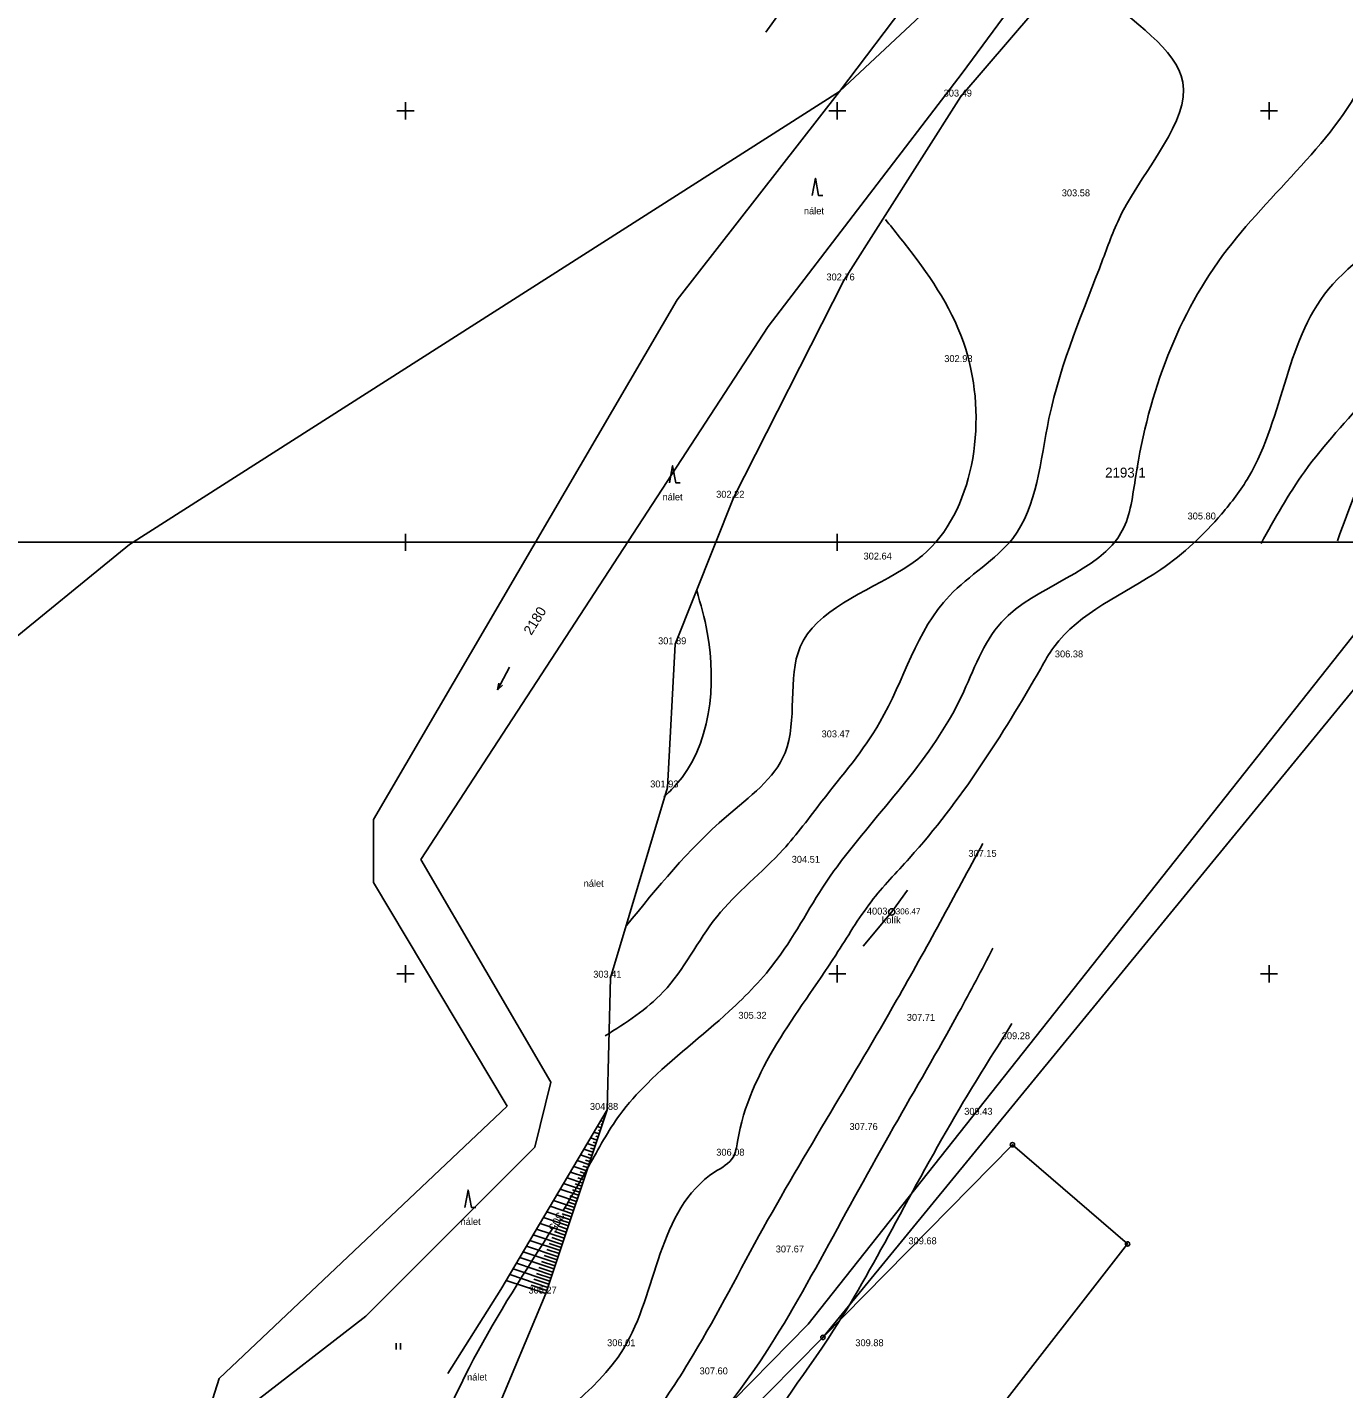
# Model space of a CAD drawing. Extents: x -504375 to -503125, y -1118000 to -1116474.
# Drawn here: x -503693.8 to -503541.3, y -1117098.1 to -1116940.3 of the extents above; entities that cross this region are included whole.
import ezdxf

# ---------------------------------------------------------------- set-up
doc = ezdxf.new("R2010")
doc.units = 0
for name, color, linetype in [('Druhy povrchů', 7, 'Continuous'), ('Podkladové mapy', 7, 'Continuous'), ('Síť dekadická', 7, 'Continuous'), ('Vrstva 34', 7, 'Continuous'), ('Vrstva 48', 7, 'Continuous'), ('Výškopis', 7, 'Continuous'), ('Výšky bod_ pole', 7, 'Continuous'), ('Výšky bodů plotr', 7, 'Continuous'), ('Čísla bod_ pole', 7, 'Continuous')]:
    doc.layers.add(name, color=color, linetype=linetype)

msp = doc.modelspace()

# ---------------------------------------------------------------- linework, layer by layer
at = {"layer": 'Druhy povrchů'}
for p, q in [((-503651.096, -1117093.521), (-503651.096, -1117092.771)), ((-503650.596, -1117093.521), (-503650.596, -1117092.771))]:
    msp.add_line(p, q, dxfattribs=at)
for points in [[(-503608.29, -1116940.921), (-503586.95, -1116911.2)], [(-503626.65, -1117065.74), (-503626.27, -1117050.43), (-503619.67, -1117028.39), (-503618.76, -1117011.81), (-503612.03, -1116994.83), (-503599.26, -1116969.66), (-503585.68, -1116948.36), (-503569.03, -1116928.88)], [(-503602.917, -1116959.834), (-503602.542, -1116957.834), (-503602.167, -1116959.834), (-503601.667, -1116959.834)], [(-503619.45, -1116993.122), (-503619.075, -1116991.122), (-503618.7, -1116993.122), (-503618.2, -1116993.122)], [(-503643.134, -1117077.037), (-503642.759, -1117075.037), (-503642.384, -1117077.037), (-503641.884, -1117077.037)]]:
    msp.add_lwpolyline(points, dxfattribs=at)
at = {"layer": 'Podkladové mapy'}
for p, q in [((-503599.74, -1116947.77), (-503559.03, -1116909.64)), ((-503559.03, -1116909.64), (-503585.52, -1116945.65)), ((-503582.63, -1116925.15), (-503599.74, -1116947.77)), ((-503585.52, -1116945.65), (-503608.01, -1116975)), ((-503599.74, -1116947.77), (-503681.99, -1117000.24)), ((-503599.74, -1116947.77), (-503618.54, -1116971.91)), ((-503618.54, -1116971.91), (-503653.73, -1117032.11)), ((-503608.01, -1116975), (-503648.24, -1117036.74)), ((-503681.99, -1117000.24), (-503736.12, -1117044.39)), ((-503603.38, -1117090.56), (-503539.71, -1117010.12)), ((-503637.952, -1117014.442), (-503639.348, -1117017.098)), ((-503639.348, -1117017.098), (-503639.22, -1117016.318)), ((-503639.348, -1117017.098), (-503638.778, -1117016.55)), ((-503539.88, -1117016.68), (-503601.67, -1117092.1)), ((-503653.73, -1117032.11), (-503653.73, -1117039.4)), ((-503648.24, -1117036.74), (-503633.18, -1117062.52)), ((-503653.73, -1117039.4), (-503638.23, -1117065.31)), ((-503633.18, -1117062.52), (-503635.02, -1117070.06)), ((-503638.23, -1117065.31), (-503671.6, -1117096.86)), ((-503635.02, -1117070.06), (-503654.6, -1117089.64)), ((-503601.67, -1117092.1), (-503579.71, -1117069.78)), ((-503579.71, -1117069.78), (-503566.38, -1117081.28)), ((-503566.38, -1117081.28), (-503584.24, -1117104.21)), ((-503654.6, -1117089.64), (-503668.48, -1117100.36)), ((-503629.16, -1117116.82), (-503603.38, -1117090.56)), ((-503601.67, -1117092.1), (-503628.2, -1117118.94)), ((-503671.6, -1117096.86), (-503676.34, -1117111.82))]:
    msp.add_line(p, q, dxfattribs=at)
for centre, radius in [((-503579.71, -1117069.78), 0.25), ((-503579.71, -1117069.78), 0.005), ((-503566.38, -1117081.28), 0.25), ((-503566.38, -1117081.28), 0.005), ((-503601.67, -1117092.1), 0.25), ((-503601.67, -1117092.1), 0.005)]:
    msp.add_circle(centre, radius, dxfattribs=at)
at = {"layer": 'Síť dekadická'}
for points in [[(-503125, -1116500), (-503125, -1117000), (-503750, -1117000), (-503750, -1116500)], [(-503125, -1117000), (-503125, -1117500), (-503750, -1117500), (-503750, -1117000)]]:
    msp.add_lwpolyline(points, close=True, dxfattribs=at)
at = {"layer": 'Vrstva 34'}
for p, q in [((-503649, -1116950), (-503651, -1116950)), ((-503650, -1116949), (-503650, -1116951)), ((-503599, -1116950), (-503601, -1116950)), ((-503600, -1116949), (-503600, -1116951)), ((-503549, -1116950), (-503551, -1116950)), ((-503550, -1116949), (-503550, -1116951)), ((-503650, -1116999), (-503650, -1117001)), ((-503600, -1116999), (-503600, -1117001)), ((-503649, -1117000), (-503651, -1117000)), ((-503599, -1117000), (-503601, -1117000)), ((-503650, -1117049), (-503650, -1117051)), ((-503600, -1117049), (-503600, -1117051)), ((-503550, -1117049), (-503550, -1117051)), ((-503649, -1117050), (-503651, -1117050)), ((-503599, -1117050), (-503601, -1117050)), ((-503549, -1117050), (-503551, -1117050))]:
    msp.add_line(p, q, dxfattribs=at)
msp.add_lwpolyline([(-503819.807, -1117000), (-503275.634, -1117000)], dxfattribs=at)
at = {"layer": 'Vrstva 48'}
for points in [[(-503604.648, -1116893.017), (-503585.281, -1116877.629), (-503564.204, -1116856.163), (-503559.141, -1116846.411), (-503555.47, -1116841.092), (-503545.09, -1116825.515), (-503541.545, -1116820.955), (-503537.748, -1116809.05), (-503527.661, -1116795.622), (-503512.228, -1116780.775), (-503494.197, -1116771.273), (-503473.272, -1116763.329), (-503471.937, -1116764.072), (-503472.777, -1116780.406), (-503472.777, -1116784.258), (-503469.477, -1116780.647), (-503453.941, -1116763.075), (-503453.185, -1116762.352), (-503453.185, -1116762.868), (-503453.975, -1116764.072), (-503471.299, -1116785.427), (-503472.33, -1116786.837), (-503470.852, -1116786.39), (-503455.075, -1116781.507), (-503451.26, -1116777.243), (-503444.179, -1116769.093), (-503443.526, -1116769.574), (-503443.526, -1116770.571), (-503444.695, -1116772.291), (-503475.689, -1116813.651), (-503482.752, -1116823.597), (-503483.629, -1116833.318), (-503494.224, -1116852.196), (-503500.83, -1116876.786), (-503505.671, -1116884.199), (-503502.737, -1116897.996), (-503507.864, -1116915.207), (-503507.864, -1116918.075), (-503510.659, -1116921.875), (-503514.672, -1116929.547), (-503521.782, -1116946.335), (-503523.508, -1116955.336), (-503526.664, -1116975.16), (-503536.264, -1116987.26), (-503542.078, -1116999.845)], [(-503595.76, -1116904.33), (-503567.553, -1116880.477), (-503564.659, -1116878.465), (-503551.807, -1116863.496), (-503544.154, -1116853.288), (-503519.921, -1116831.988), (-503513.226, -1116822.631), (-503501.21, -1116822.631), (-503499.538, -1116822.631), (-503498.221, -1116820.86), (-503490.256, -1116808.462), (-503490.097, -1116808.462), (-503490.242, -1116808.76), (-503498.304, -1116822.118), (-503497.349, -1116823.505), (-503494.998, -1116824.802), (-503494.566, -1116824.802), (-503486.255, -1116822.916), (-503485.421, -1116822.675), (-503484.37, -1116821.039), (-503476.855, -1116810.755), (-503475.486, -1116809.268), (-503476.662, -1116811.094), (-503489.122, -1116830.174), (-503489.781, -1116831.15), (-503492.54, -1116830.63), (-503502.814, -1116846.355), (-503503.817, -1116849.106), (-503512.403, -1116878.631), (-503514.977, -1116882.212), (-503509.347, -1116898.468), (-503509.347, -1116900.238), (-503513.047, -1116914.643), (-503520.593, -1116930.622), (-503522.926, -1116936.361), (-503526.804, -1116946.842), (-503527.79, -1116953.008), (-503531.841, -1116973.659), (-503545.886, -1116991.815), (-503550.918, -1117000.124)], [(-503583.436, -1116916.735), (-503565.222, -1116898.002), (-503545.734, -1116881.633), (-503534.572, -1116870.778), (-503513.205, -1116846.809), (-503510.867, -1116843.732), (-503510.418, -1116843.732), (-503511.603, -1116846.232), (-503518.586, -1116862.77), (-503523.84, -1116880.397), (-503523.84, -1116881.294), (-503515.357, -1116898.665), (-503516.275, -1116901.249), (-503527.394, -1116929.845), (-503527.394, -1116936.169), (-503527.485, -1116936.022), (-503531.377, -1116947.63), (-503532.293, -1116950.302), (-503533.896, -1116960.764), (-503542.598, -1116970.081), (-503552.37, -1116992.445), (-503555.496, -1116996.72), (-503562.532, -1117003.134), (-503574.935, -1117012.154), (-503576.446, -1117014.604), (-503591.634, -1117036.568), (-503596.086, -1117041.635), (-503600.171, -1117047.806), (-503611.566, -1117069.423), (-503612.057, -1117071.221), (-503614.181, -1117072.938), (-503624.76, -1117093.42), (-503637.766, -1117106.652), (-503639.522, -1117109.013), (-503645.943, -1117120.982), (-503647.205, -1117123.178), (-503648.851, -1117124.99), (-503653.281, -1117132.788), (-503655.18, -1117135.25), (-503664.808, -1117144.375), (-503670.8, -1117145.499), (-503672.957, -1117151.15), (-503675.518, -1117162.241), (-503680.888, -1117175.407), (-503686.593, -1117176.265), (-503690.913, -1117183.112)], [(-503575.161, -1116925.677), (-503571.61, -1116920.286), (-503561.49, -1116904.84), (-503546.317, -1116891.936), (-503543.581, -1116890.008), (-503545.449, -1116892.274), (-503560.054, -1116907.893), (-503567.245, -1116921.98), (-503572.354, -1116932.827), (-503569.7, -1116936.145), (-503559.991, -1116946.69), (-503567.028, -1116961.847), (-503569.227, -1116967.176), (-503575.482, -1116985.657), (-503579.685, -1116999.542), (-503587.015, -1117006.191), (-503595.059, -1117020.842), (-503601.786, -1117029.99), (-503606.272, -1117035.599), (-503613.948, -1117043.366), (-503620.158, -1117052.082), (-503626.886, -1117057.173)], [(-503536.643, -1116939.897), (-503538.176, -1116944.585), (-503554.835, -1116966.082), (-503565.428, -1116992.282), (-503566.988, -1116998.644), (-503580.982, -1117009.239), (-503585.615, -1117017.847), (-503599.496, -1117036.863), (-503600.903, -1117038.792), (-503606.947, -1117048.279), (-503612.516, -1117054.325), (-503622.032, -1117062.711), (-503625.19, -1117066.316), (-503628.794, -1117072.271), (-503631.697, -1117077.316)], [(-503624.405, -1117044.39), (-503612.833, -1117031.761), (-503606.053, -1117024.393), (-503604.3, -1117012.114), (-503592.377, -1117003.109), (-503590.138, -1117001.513), (-503584.884, -1116978.453), (-503591.259, -1116966.607), (-503594.412, -1116962.612)], [(-503620.074, -1117029.483), (-503618.701, -1117028.109), (-503615.064, -1117010.433), (-503616.288, -1117005.569)], [(-503681.581, -1117189.358), (-503677.862, -1117181.382), (-503666.722, -1117185.997), (-503660.312, -1117176.769), (-503662.273, -1117171.205), (-503665.544, -1117166.288), (-503664.496, -1117159.63), (-503663.424, -1117157.82), (-503656.724, -1117146.894), (-503651.699, -1117143.274), (-503642.136, -1117131.351), (-503640.456, -1117128.532), (-503633.339, -1117117.852), (-503629.848, -1117112.023), (-503622.694, -1117102.978), (-503617.219, -1117095.012), (-503609.076, -1117080.347), (-503600.768, -1117066.026), (-503593.131, -1117053.049), (-503583.142, -1117034.879)], [(-503670.377, -1117191.619), (-503669.68, -1117189.038), (-503667.476, -1117187.838), (-503659.224, -1117178.665), (-503659.729, -1117171.664), (-503658.467, -1117166.241), (-503646.499, -1117149.509), (-503636.524, -1117137.367), (-503628.369, -1117122.514), (-503620.153, -1117109.423), (-503610.19, -1117096.668), (-503601.485, -1117082.212), (-503593.478, -1117067.759), (-503585.924, -1117054.445), (-503581.971, -1117047.028)], [(-503663.774, -1117189.171), (-503657.669, -1117182.299), (-503653.803, -1117173.825), (-503650.734, -1117168.851), (-503649.206, -1117166.706), (-503639.945, -1117154.236), (-503631.523, -1117142.215), (-503623.535, -1117130.705), (-503616.437, -1117119.955), (-503611.15, -1117107.935), (-503600.425, -1117091.261), (-503593.212, -1117078.753), (-503585.366, -1117064.793), (-503579.769, -1117055.757)], [(-503632.866, -1117079.324), (-503648.483, -1117110.842), (-503649.96, -1117118.382), (-503650.49, -1117120.413), (-503659.36, -1117127.451), (-503663.602, -1117129.909)]]:
    msp.add_spline(points, degree=3, dxfattribs=at)
at = {"layer": 'Výškopis'}
for p, q in [((-503627.107, -1117067.105), (-503627.4, -1117067.007)), ((-503626.988, -1117066.75), (-503627.074, -1117066.721)), ((-503626.869, -1117066.394), (-503627.009, -1117066.347)), ((-503626.75, -1117066.038), (-503626.775, -1117066.03)), ((-503627.583, -1117068.528), (-503628.181, -1117068.328)), ((-503627.345, -1117067.816), (-503627.79, -1117067.667)), ((-503627.464, -1117068.172), (-503627.673, -1117068.102)), ((-503627.226, -1117067.461), (-503627.374, -1117067.411)), ((-503628.059, -1117069.95), (-503628.962, -1117069.648)), ((-503627.821, -1117069.239), (-503628.572, -1117068.988)), ((-503628.178, -1117070.306), (-503628.57, -1117070.175)), ((-503627.94, -1117069.595), (-503628.271, -1117069.484)), ((-503627.702, -1117068.883), (-503627.972, -1117068.793)), ((-503628.773, -1117072.084), (-503630.134, -1117071.628)), ((-503628.535, -1117071.373), (-503629.744, -1117070.968)), ((-503628.297, -1117070.661), (-503629.353, -1117070.308)), ((-503628.654, -1117071.728), (-503629.168, -1117071.556)), ((-503628.416, -1117071.017), (-503628.869, -1117070.865)), ((-503629.249, -1117073.506), (-503630.915, -1117072.948)), ((-503629.011, -1117072.795), (-503630.525, -1117072.288)), ((-503629.13, -1117073.151), (-503629.766, -1117072.938)), ((-503628.892, -1117072.439), (-503629.467, -1117072.247)), ((-503629.962, -1117075.64), (-503632.087, -1117074.929)), ((-503629.724, -1117074.929), (-503631.697, -1117074.269)), ((-503629.486, -1117074.218), (-503631.306, -1117073.609)), ((-503629.605, -1117074.573), (-503630.364, -1117074.319)), ((-503629.368, -1117073.862), (-503630.065, -1117073.629)), ((-503630.438, -1117077.063), (-503632.868, -1117076.249)), ((-503630.2, -1117076.351), (-503632.478, -1117075.589)), ((-503630.319, -1117076.707), (-503631.261, -1117076.392)), ((-503630.081, -1117075.996), (-503630.962, -1117075.701)), ((-503629.843, -1117075.284), (-503630.663, -1117075.01)), ((-503630.914, -1117078.485), (-503633.65, -1117077.57)), ((-503630.676, -1117077.774), (-503633.259, -1117076.91)), ((-503630.795, -1117078.129), (-503631.859, -1117077.774)), ((-503630.557, -1117077.418), (-503631.56, -1117077.083)), ((-503631.628, -1117080.619), (-503634.822, -1117079.55)), ((-503631.39, -1117079.908), (-503634.431, -1117078.89)), ((-503631.152, -1117079.196), (-503634.04, -1117078.23)), ((-503631.271, -1117079.552), (-503632.457, -1117079.155)), ((-503631.033, -1117078.841), (-503632.158, -1117078.464)), ((-503632.104, -1117082.041), (-503635.603, -1117080.87)), ((-503631.866, -1117081.33), (-503635.212, -1117080.21)), ((-503631.985, -1117081.686), (-503633.354, -1117081.228)), ((-503631.747, -1117080.974), (-503633.055, -1117080.537)), ((-503631.509, -1117080.263), (-503632.756, -1117079.846)), ((-503632.818, -1117084.175), (-503636.775, -1117082.851)), ((-503632.58, -1117083.464), (-503636.384, -1117082.191)), ((-503632.342, -1117082.753), (-503635.993, -1117081.531)), ((-503632.461, -1117083.108), (-503633.952, -1117082.609)), ((-503632.223, -1117082.397), (-503633.653, -1117081.918)), ((-503633.294, -1117085.598), (-503637.556, -1117084.172)), ((-503633.056, -1117084.886), (-503637.165, -1117083.511)), ((-503632.937, -1117084.531), (-503634.55, -1117083.991)), ((-503632.699, -1117083.819), (-503634.251, -1117083.3)), ((-503633.77, -1117087.02), (-503638.337, -1117085.492)), ((-503633.532, -1117086.309), (-503637.947, -1117084.832)), ((-503633.413, -1117085.953), (-503635.148, -1117085.372)), ((-503633.175, -1117085.242), (-503634.849, -1117084.682)), ((-503633.651, -1117086.664), (-503635.447, -1117086.063))]:
    msp.add_line(p, q, dxfattribs=at)
for points in [[(-503626.65, -1117065.74), (-503638.975, -1117086.57), (-503645.112, -1117096.276)], [(-503633.77, -1117087.02), (-503626.65, -1117065.74)], [(-503643.15, -1117107.78), (-503640.92, -1117104.15), (-503633.77, -1117087.02)]]:
    msp.add_lwpolyline(points, dxfattribs=at)
at = {"layer": 'Čísla bod_ pole'}
msp.add_lwpolyline([(-503597.002, -1117046.78), (-503593.7, -1117042.82), (-503591.888, -1117040.277)], dxfattribs=at)
for radius in [0.375, 0.0005]:
    msp.add_circle((-503593.7, -1117042.82), radius, dxfattribs=at)

# ---------------------------------------------------------------- texts
at = {"layer": 'Druhy povrchů'}
for p in [(-503603.866, -1116962.003), (-503620.239, -1116995.145), (-503629.377, -1117039.906), (-503643.629, -1117079.081), (-503642.879, -1117097.092)]:
    msp.add_text('nálet', height=0.8, dxfattribs=at).set_placement(p)
at = {"layer": 'Podkladové mapy'}
msp.add_text('2193/1', height=1.15, dxfattribs=at).set_placement((-503568.977, -1116992.495))
msp.add_text('2180', height=1.15, rotation=58.33341, dxfattribs=at).set_placement((-503635.44, -1117010.84))
at = {"layer": 'Vrstva 48'}
msp.add_text('305', height=1, rotation=239.78728, dxfattribs=at).set_placement((-503632.38, -1117077.497))
at = {"layer": 'Výšky bod_ pole'}
msp.add_text('306.47 ', height=0.7, dxfattribs=at).set_placement((-503593.234, -1117043.1))
at = {"layer": 'Výšky bodů plotr'}
for s, p in [('303.49 ', (-503587.68, -1116948.36)), ('303.58 ', (-503574, -1116959.92)), ('302.76 ', (-503601.26, -1116969.66)), ('302.98 ', (-503587.61, -1116979.12)), ('302.22 ', (-503614.03, -1116994.83)), ('305.80 ', (-503559.43, -1116997.35)), ('302.64 ', (-503596.96, -1117001.99)), ('301.89 ', (-503620.76, -1117011.81)), ('306.38 ', (-503574.8, -1117013.33)), ('303.47 ', (-503601.82, -1117022.59)), ('301.93 ', (-503621.67, -1117028.39)), ('304.51 ', (-503605.28, -1117037.12)), ('307.15 ', (-503584.82, -1117036.43)), ('303.41 ', (-503628.27, -1117050.43)), ('305.32 ', (-503611.46, -1117055.19)), ('307.71 ', (-503591.95, -1117055.43)), ('309.28 ', (-503580.95, -1117057.56)), ('304.88 ', (-503628.65, -1117065.74)), ('309.43 ', (-503585.3, -1117066.31)), ('307.76 ', (-503598.59, -1117068.07)), ('306.08 ', (-503614.02, -1117071.05)), ('309.68 ', (-503591.76, -1117081.31)), ('307.67 ', (-503607.13, -1117082.26)), ('305.27 ', (-503635.77, -1117087.02)), ('306.01 ', (-503626.66, -1117093.12)), ('309.88 ', (-503597.91, -1117093.12)), ('307.60 ', (-503615.95, -1117096.38))]:
    msp.add_text(s, height=0.8, dxfattribs=at).set_placement(p)
at = {"layer": 'Čísla bod_ pole'}
for s, p in [('4003', (-503596.574, -1117043.122)), ('kolík', (-503594.853, -1117044.148))]:
    msp.add_text(s, height=0.8, dxfattribs=at).set_placement(p)

doc.saveas('drawing.dxf')
